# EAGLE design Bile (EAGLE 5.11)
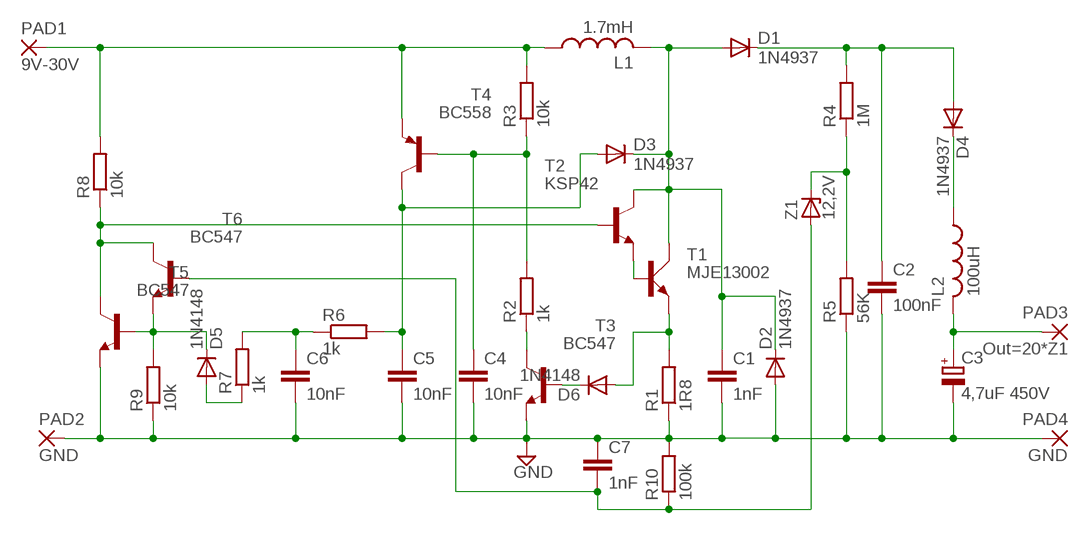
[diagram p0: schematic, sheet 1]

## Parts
C1  1nF  C-EU050-025X075  [C050-025X075]
C2  100nF  C-EU102-043X133  [C102-043X133]
C3  4,7uF 450V  CPOL-EUE5-10.5  [E5-10,5]
C4  10nF  C-EU050-025X075  [C050-025X075]
C5  10nF  C-EU050-025X075  [C050-025X075]
C6  10nF  C-EU050-025X075  [C050-025X075]
C7  1nF  C-EU050-025X075  [C050-025X075]
D1  1N4937  1N4148DO35-7  [DO35-7]
D2  1N4937  1N4148DO35-7  [DO35-7]
D3  1N4937  1N4148DO35-7  [DO35-7]
D4  1N4937  1N4148DO35-7  [DO35-7]
D5  1N4148  1N4148DO35-7  [DO35-7]
D6  1N4148  1N4148DO35-7  [DO35-7]
L1  1.7mH  L-USL-TRAFO  [TRAFO16MM]
L2  100uH  L-USTFI0510  [TFI0510]
PAD1  9V-30V  2,54/0,8  [2,54/0,8]
PAD2  GND  2,54/0,8  [2,54/0,8]
PAD3  Out=20*Z1  2,54/0,8  [2,54/0,8]
PAD4  GND  2,54/0,8  [2,54/0,8]
R1  1R8  R-EU_0204/7  [0204/7]
R2  1k  R-EU_0204/7  [0204/7]
R3  10k  R-EU_0204/7  [0204/7]
R4  1M  R-EU_0204/7  [0204/7]
R5  56K  R-EU_0204/7  [0204/7]
R6  1k  R-EU_0204/7  [0204/7]
R7  1k  R-EU_0204/7  [0204/7]
R8  10k  R-EU_0204/7  [0204/7]
R9  10k  R-EU_0204/7  [0204/7]
R10  100k  R-EU_0204/7  [0204/7]
T1  MJE13002  TIP41C  [TO220AV]
T2  KSP42  -NPN-TO92-EBC  [TO92-EBC]
T3  BC547  -NPN-TO92-CBE  [TO92-CBE]
T4  BC558  -PNP-TO92-CBE  [TO92-CBE]
T5  BC547  -NPN-TO92-CBE  [TO92-CBE]
T6  BC547  -NPN-TO92-CBE  [TO92-CBE]
Z1  12,2V  ZPY  [DO41Z10]

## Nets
GND: C1.2 C2.2 C3.- C4.2 C5.2 C6.2 C7.1 D2.A PAD2.1(P) PAD4.1(P) R1.1 R5.1 R9.1 R10.2 T3.E T5.E
N$1: D4.C L2.1
N$2: D6.A R1.2 T1.E
N$3: T1.B T2.E
N$4: C1.1 D1.A D2.C D3.C L1.P$7 T1.C T2.C
N$5: L1.P$5 PAD1.1(P) R3.2 R8.2 T4.E
N$6: C4.1 R2.2 R3.1 T4.B
N$7: R2.1 T3.C
N$8: C3.+ L2.2 PAD3.1(P)
N$9: C2.1 D1.C D4.A R4.2
N$10: R4.1 R5.2 Z1.C
N$11: C7.2 R10.1 T6.B Z1.A
N$12: C5.1 D3.A R6.2 T4.C
N$13: D5.A R7.1
N$14: C6.1 R6.1 R7.2
N$15: D6.C T3.B
N$16: D5.C R9.2 T5.B T6.E
N$17: R8.1 T2.B T5.C T6.C

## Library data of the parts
C1 C2 C4-C7 = rcl:C-EU: CAPACITOR, European symbol
C3 = rcl:CPOL-EU: POLARIZED CAPACITOR, European symbol
D1-D6 = diode:1N4148: DIODE
L1 = Inductors:L-US: INDUCTOR, American symbol
L2 = rcl:L-US: INDUCTOR, American symbol
PAD1-PAD4 = wirepad:2,54/0,8: THROUGH-HOLE PAD
R1-R10 = rcl:R-EU_: RESISTOR, European symbol
T1 = transistor-power:TIP41C: NPN TRANSISTOR
T2 T3 T5 T6 = transistor-neu-to92:*-NPN-: NPN Transistror
T4 = transistor-neu-to92:*-PNP-: PNP Transistror
Z1 = diode:ZPY: Z DIODE

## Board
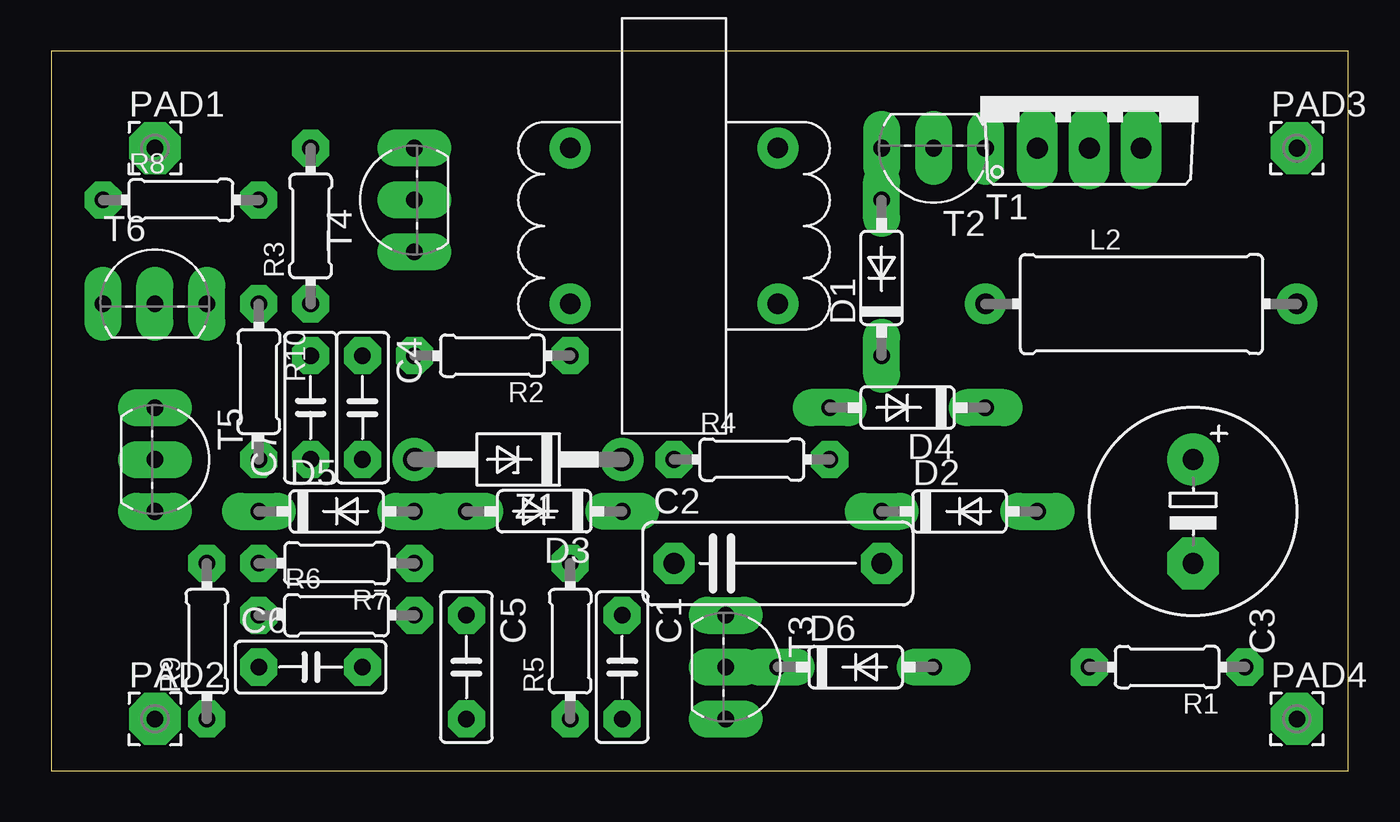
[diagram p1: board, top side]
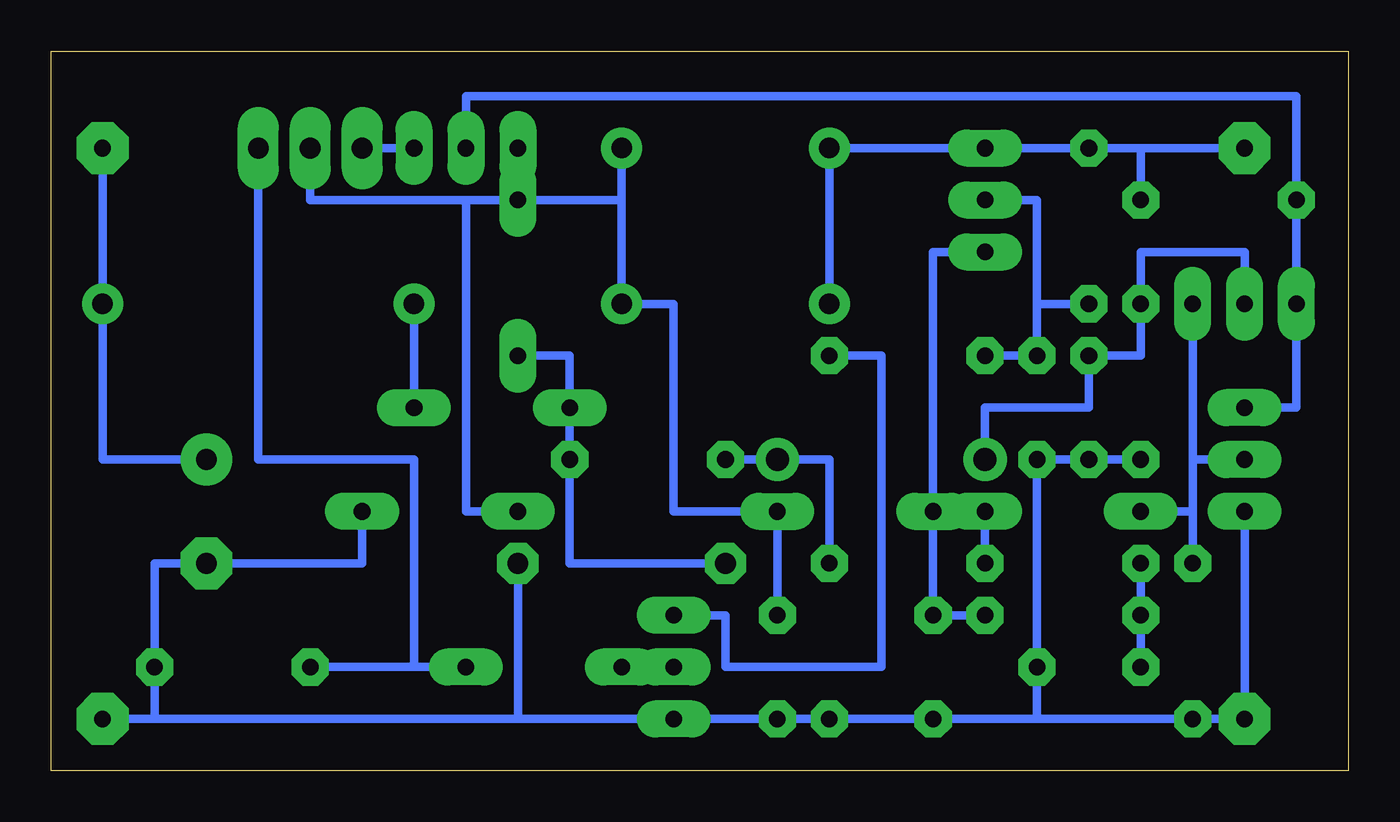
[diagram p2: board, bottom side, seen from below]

Size 63.48 x 35.23 mm. Coordinates in mm from the lower left corner, seen from the top.
Outline: 0,0 63.48,0 63.48,35.23 0,35.23 0,0
Copper layers (1*16): Top 0.035mm / dielectric 1.5mm / Bottom 0.035mm
Design rules "Manual": minimum track width 0.7mm, minimum drill 0.5mm, track to track 0.5mm, track to pad 0.5mm, pad to pad 0.5mm, via to via 1mm, smd to smd 8mil, copper to edge 40mil, drill to drill 1mm, minimum pad ring 0.5mm, minimum via ring 0.5mm, stop-mask expansion 4mil, vias tented up to drill 0mil, thermal gap 10mil

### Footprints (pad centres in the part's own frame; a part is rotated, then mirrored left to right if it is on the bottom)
C050-025X075 = drill 0.813 octagon: 1 -2.54,0; 2 2.54,0
C102-043X133 = drill 1.016 octagon: 1 -5.08,0; 2 5.08,0
E5-10,5 = drill 1.016 pad 2.54 round: + -2.54,0 | drill 1.016 pad 2.54 octagon: - 2.54,0
DO35-7 = drill 0.813 long: A 3.81,0; C -3.81,0
TRAFO16MM = drill 1 round: P$5 -3.81,5.08; P$6 3.81,5.08; P$7 -3.81,-5.08; P$8 3.81,-5.08
TFI0510 = drill 1 pad 1.6 round: 1 -7.62,0; 2 7.62,0
2,54/0,8 = drill 0.813 pad 2.54 octagon: 1 0,0
0204/7 = drill 0.813 octagon: 1 -3.81,0; 2 3.81,0
TO220AV = drill 1.016 long: B -2.54,-2.54; C 0,-2.54; E 2.54,-2.54
TO92-EBC = drill 0.813 long: B 0,-1.27; C 2.54,-1.27; E -2.54,-1.27
TO92-CBE = drill 0.813 long: B 0,0; C -2.54,0; E 2.54,0
DO41Z10 = drill 1.118 round: A 5.08,0; C -5.08,0

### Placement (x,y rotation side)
C1  27.94,5.08 270 top
C2  35.56,10.16 0 top
C3  55.88,12.7 270 top
C4  15.24,17.78 270 top
C5  20.32,5.08 270 top
C6  12.7,5.08 0 top
C7  12.7,17.78 90 top
D1  40.64,24.13 90 top
D2  44.45,12.7 0 top
D3  24.13,12.7 180 top
D4  41.91,17.78 180 top
D5  13.97,12.7 0 top
D6  39.37,5.08 0 top
L1  30.48,26.67 90 top
L2  53.34,22.86 0 top
PAD1  5.08,30.48 0 top
PAD2  5.08,2.54 0 top
PAD3  60.96,30.48 0 top
PAD4  60.96,2.54 0 top
R1  54.61,5.08 180 top
R2  21.59,20.32 180 top
R3  12.7,26.67 90 top
R4  34.29,15.24 0 top
R5  25.4,6.35 90 top
R6  13.97,7.62 0 top
R7  13.97,10.16 180 top
R8  6.35,27.94 0 top
R9  7.62,6.35 90 top
R10  10.16,19.05 270 top
T1  50.8,33.02 0 top
T2  43.18,29.21 180 top
T3  33.02,5.08 270 top
T4  17.78,27.94 90 top
T5  5.08,15.24 270 top
T6  5.08,22.86 0 top
Z1  22.86,15.24 180 top

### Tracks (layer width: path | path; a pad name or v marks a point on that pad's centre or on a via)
GND
  Bottom 0.406: 15.24,2.54 R9.1 PAD2.1 T5.E | 15.24,2.54 C6.2 C4.2 C7.1 R10.2 | 15.24,2.54 C5.2 | C5.2 C1.2 T3.E 40.64,2.54 | C5.2 R5.1 | 40.64,2.54 C2.2 | 40.64,2.54 58.42,2.54 | 58.42,2.54 PAD4.1 | 58.42,2.54 R1.1 58.42,10.16 C3.- 48.26,10.16 D2.A
N$1
  Bottom 0.406: D4.C L2.1
N$2
  Bottom 0.406: D6.A 45.72,5.08 | 45.72,5.08 R1.2 | 45.72,5.08 45.72,15.24 53.34,15.24 T1.E
N$3
  Bottom 0.406: T2.E T1.B
N$4
  Bottom 0.406: 35.56,27.94 L1.P$7 33.02,22.86 33.02,12.7 D3.C C1.1 | 35.56,27.94 35.56,30.48 | T1.C 50.8,27.94 D1.A | 43.18,27.94 43.18,12.7 D2.C | 35.56,27.94 D1.A | D1.A T2.C
N$5
  Bottom 0.406: PAD1.1 10.16,30.48 | 10.16,30.48 R3.2 T4.E 25.4,30.48 L1.P$5 | 10.16,30.48 R8.2
N$6
  Bottom 0.406: 15.24,22.86 C4.1 R2.2 | 15.24,22.86 15.24,27.94 T4.B | R3.1 15.24,22.86
N$7
  Bottom 0.406: R2.1 22.86,20.32 22.86,5.08 30.48,5.08 30.48,7.62 T3.C
N$8
  Bottom 0.406: PAD3.1 L2.2 60.96,15.24 C3.+
N$9
  Bottom 0.406: D1.C 38.1,20.32 D4.A R4.2 38.1,10.16 C2.1
N$10
  Bottom 0.406: R4.1 Z1.C 25.4,15.24 R5.2
N$11
  Bottom 0.406: T6.B 5.08,25.4 10.16,25.4 R10.1 10.16,20.32 C7.2 12.7,17.78 17.78,17.78 Z1.A
N$12
  Bottom 0.406: R6.2 C5.1 D3.A 20.32,25.4 T4.C
N$13
  Bottom 0.406: D5.A R7.1
N$14
  Bottom 0.406: R7.2 R6.1 C6.1
N$15
  Bottom 0.406: T3.B D6.C
N$16
  Bottom 0.406: 7.62,12.7 D5.C | R9.2 7.62,12.7 | 7.62,12.7 7.62,15.24 | 7.62,15.24 T6.E | 7.62,15.24 T5.B
N$17
  Bottom 0.406: T5.C 2.54,17.78 T6.C R8.1 2.54,33.02 43.18,33.02 T2.B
